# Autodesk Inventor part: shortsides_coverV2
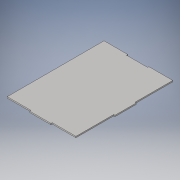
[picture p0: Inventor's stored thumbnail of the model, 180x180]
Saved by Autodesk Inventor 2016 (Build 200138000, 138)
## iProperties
Created: 2015-11
Part Number: shortsides_coverV2
Material: Generic
Document SubType Name: Modeling
Designer: silverd
Density: 1 g/cm^3
Appearance: Default
Author: silverd
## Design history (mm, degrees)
sketch "Sketch1"
  geometry: L1 (0, 0)-(56.604, 0); L2 (164.008, 0)-(164.008, -231.194); L3 (164.008, -231.194)-(107.404, -231.194); L4 (0, -231.194)-(0, -140.997); L5 (56.604, 3)-(107.404, 3); L6 (107.404, 3)-(107.404, 0); L7 (56.604, 0)-(56.604, 3); L8 (0, -90.197)-(-3, -90.197); L9 (-3, -90.197)-(-3, -140.997); L10 (-3, -140.997)-(0, -140.997); L11 (107.404, 0)-(164.008, 0); L12 (0, -90.197)-(0, 0); L13 (56.604, -231.194)-(0, -231.194); L14 (107.213, -228.194)-(56.794, -228.194); L15 (56.794, -228.194)-(56.794, -231.194); L16 (107.213, -231.194)-(107.213, -228.194); L17 (164.008, -231.194)-(107.213, -231.194); L18 (56.794, -231.194)-(0, -231.194); 2 further points
  constraints: 36 end point, 9 parallel, 7 perpendicular, 5 horizontal
  dimensions: "d0" = 164.0078 distance of L2.end L4.start (= cover_h_nobase); "d1" = 231.1936 distance of L2.start L2.end (= cover_w + acrylic); "d2" = 50.8 distance of L6.end L1.end (= tab_w); "d3" = 3 distance of L5.end L6.end (= acrylic); "d6" = 3 distance of L4.end L9.end (= acrylic); "d7" = 50.8 distance of L9.end L8.end (= tab_w); "d10" = 50.419 distance of L16.start L15.end (= tab_w - t); "d11" = 3 distance of L15.end L14.end (= acrylic)
extrude "Extrusion1" new body sketch "Sketch1" distance "d8" = 3 (= acrylic); taper "d9" = 0 deg
body "Solid1"
other parameters: "cover_l" = 291.6936 [user parameter], "cover_w" = 228.1936 [user parameter; used in 1 equation term], "cover_h_nobase" = 164.0078 [user parameter; used in 1 equation term], "acrylic" = 3 [user parameter; used in 5 equation terms], "t" = 0.381 [user parameter; used in 1 equation term], "tab_w" = 50.8 [user parameter; used in 3 equation terms]
